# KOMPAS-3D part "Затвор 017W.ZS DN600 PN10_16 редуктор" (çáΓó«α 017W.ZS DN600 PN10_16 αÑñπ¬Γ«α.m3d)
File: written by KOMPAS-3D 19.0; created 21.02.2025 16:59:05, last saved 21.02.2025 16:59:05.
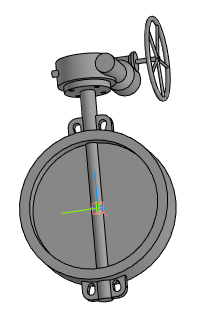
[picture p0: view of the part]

Document properties: Автор: Евгений; Полное имя файла: Затвор 017W.ZS DN600 PN10_16 редуктор.a3d

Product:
- Part/product: Затвор 017W.ZS DN600 PN10_16 редуктор
    Масса: 276.933

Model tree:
1. Операция без истории:1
